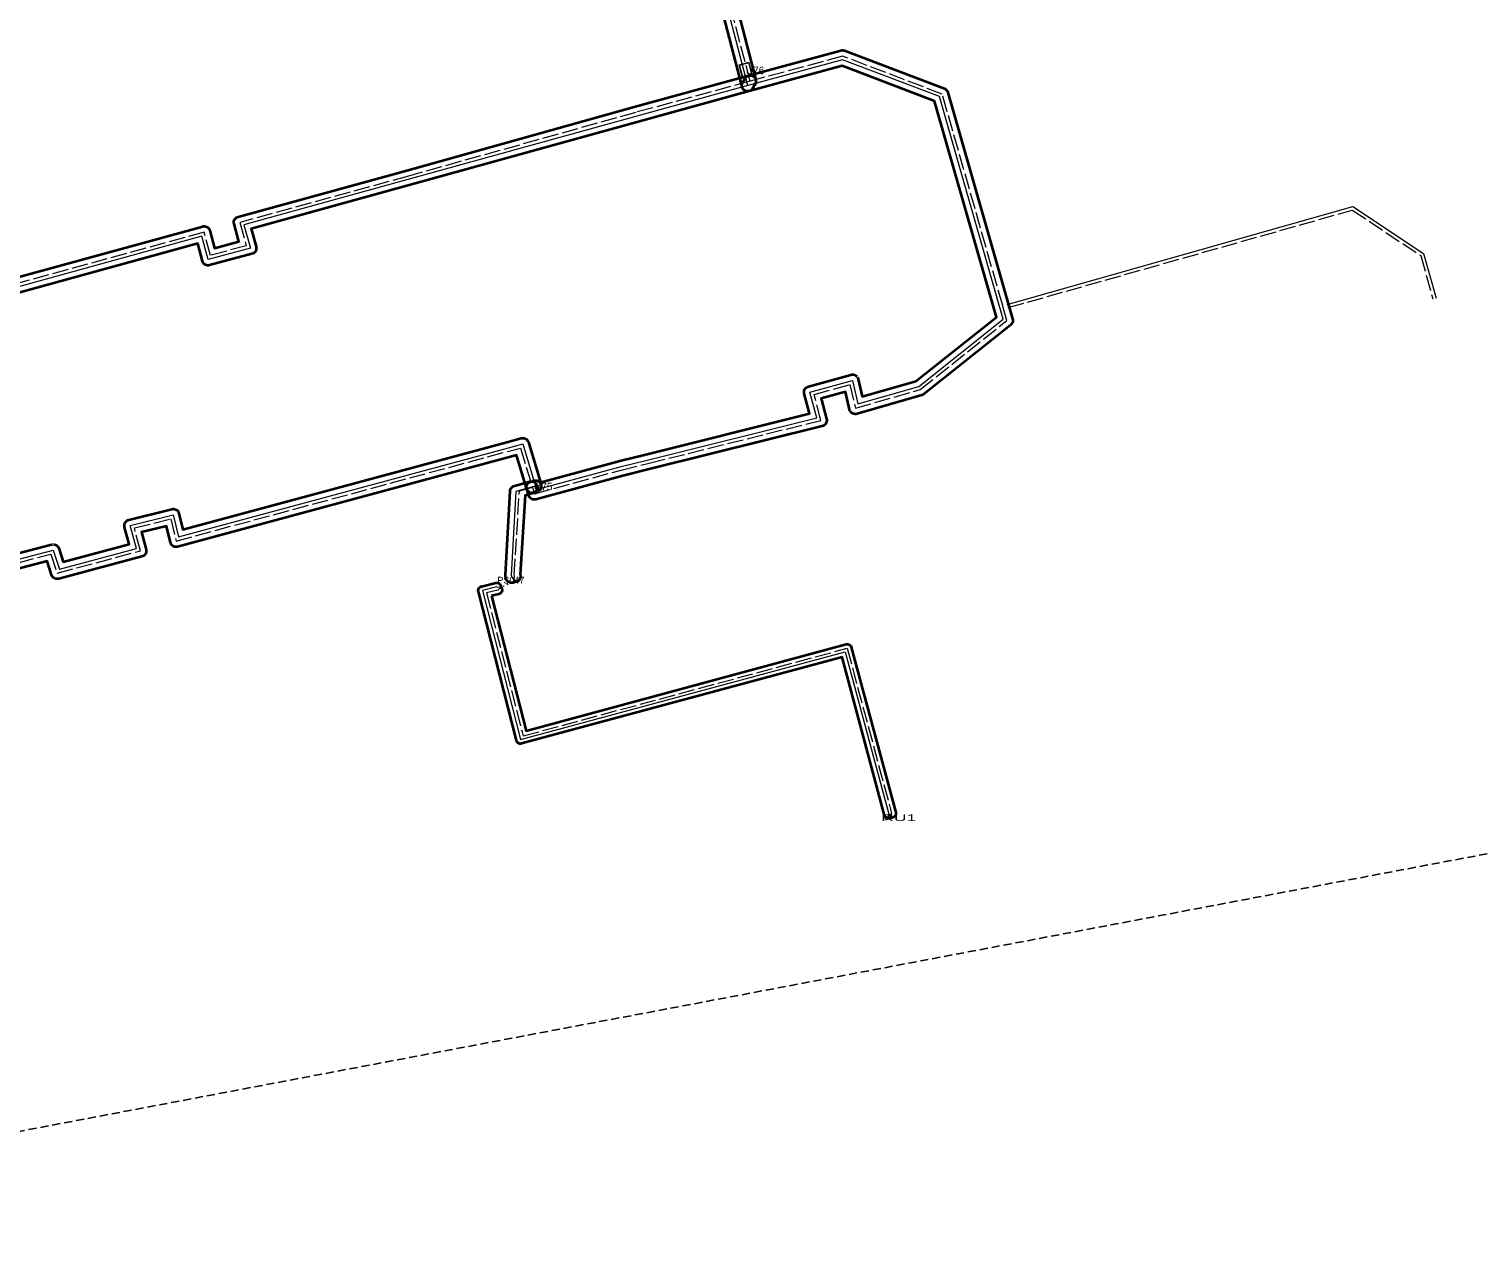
# Model space of a CAD drawing. Extents: x -452602 to -451136, y -1100088 to -1099653.
# Drawn here: x -451526.1 to -451353.5, y -1099905.8 to -1099759.5 of the extents above; entities that cross this region are included whole.
import ezdxf

# ---------------------------------------------------------------- set-up
doc = ezdxf.new("R2010")
doc.units = 0
doc.header["$LTSCALE"] = 0.32
doc.header["$PDMODE"] = 32
doc.header["$PDSIZE"] = 0.16
for name, pattern in [('DOTTED', [1.5, 0.3, -1.2]), ('LONG_DASHED', [7.5, 6, -1.5]), ('MEDIUM_DASHED', [4.5, 3, -1.5])]:
    doc.linetypes.add(name, pattern=pattern)
for name, color, linetype, lineweight in [('2', 7, 'Continuous', 13), ('3', 7, 'Continuous', 25), ('62', 7, 'MEDIUM_DASHED', 25), ('8', 7, 'Continuous', 35)]:
    doc.layers.add(name, color=color, linetype=linetype, lineweight=lineweight)
doc.layers.add('4', color=7, linetype='Continuous')

msp = doc.modelspace()

# ---------------------------------------------------------------- linework, layer by layer
at = {"layer": '2'}
for p, q in [((-451465.807, -1099813.902), (-451466.276, -1099814.026)), ((-451468.623, -1099824.703), (-451468.33, -1099825.077)), ((-451470.4, -1099825.877), (-451469.87, -1099825.911)), ((-451423.766, -1099852.933), (-451424.031, -1099853.49)), ((-451423.766, -1099852.933), (-451423.46, -1099853.339))]:
    msp.add_line(p, q, dxfattribs=at)
at = {"layer": '2', "linetype": 'LONG_DASHED'}
for p, q in [((-451466.266, -1099814.057), (-451466.163, -1099814.028)), ((-451468.33, -1099825.077), (-451468.279, -1099824.611)), ((-451470.266, -1099826.255), (-451469.87, -1099825.911)), ((-451424.031, -1099853.49), (-451423.416, -1099852.842)), ((-451423.46, -1099853.339), (-451423.416, -1099852.842))]:
    msp.add_line(p, q, dxfattribs=at)
at = {"layer": '2', "linetype": 'DOTTED'}
for q in [(-451468.33, -1099825.077), (-451469.87, -1099825.911)]:
    msp.add_line((-451469.133, -1099825.585), q, dxfattribs=at)
at = {"layer": '2'}
for points in [[(-451440.543, -1099766.212), (-451448.402, -1099735.947), (-451449.946, -1099736.35), (-451450.538, -1099734.326), (-451448.936, -1099733.888), (-451454.027, -1099714.285), (-451455.513, -1099714.714), (-451456.072, -1099712.712), (-451454.541, -1099712.309), (-451454.966, -1099710.671)], [(-451465.807, -1099813.902), (-451465.693, -1099814.283), (-451455.431, -1099811.527), (-451452.657, -1099810.837), (-451432.332, -1099805.776), (-451433.135, -1099802.708), (-451428.085, -1099801.307), (-451427.435, -1099804.116), (-451420.193, -1099802.032), (-451410.156, -1099794.026), (-451417.723, -1099767.545), (-451429.284, -1099763.151), (-451440.543, -1099766.212)], [(-451440.543, -1099766.212), (-451500.5, -1099782.791), (-451499.718, -1099785.574), (-451504.756, -1099786.93), (-451505.494, -1099784.161), (-451531.96, -1099791.453), (-451536.46, -1099775.666), (-451566.551, -1099783.675), (-451567.153, -1099781.244), (-451568.797, -1099781.667), (-451568.176, -1099784.107), (-451599.266, -1099792.381), (-451600.66, -1099787.109), (-451609.817, -1099789.576), (-451612.038, -1099780.59)], [(-451409.67, -1099792.266), (-451368.532, -1099780.606), (-451360.12, -1099786.214), (-451358.624, -1099791.515)], [(-451551.827, -1099895.315), (-451558.739, -1099869.548), (-451529.806, -1099861.951), (-451539.465, -1099825.761), (-451523.193, -1099821.5), (-451522.45, -1099823.752), (-451513.289, -1099821.307), (-451514.016, -1099818.579), (-451508.902, -1099817.3), (-451508.266, -1099819.931), (-451469.019, -1099809.326), (-451467.315, -1099808.865), (-451465.807, -1099813.902)], [(-451466.276, -1099814.026), (-451468.121, -1099814.517), (-451468.685, -1099824.471), (-451468.623, -1099824.703)], [(-451470.4, -1099825.877), (-451472.105, -1099826.309), (-451467.574, -1099844.048), (-451428.957, -1099833.619), (-451423.766, -1099852.933)]]:
    msp.add_lwpolyline(points, dxfattribs=at)
at = {"layer": '2', "linetype": 'LONG_DASHED'}
for points in [[(-451440.258, -1099765.721), (-451448.116, -1099735.46), (-451449.671, -1099735.864), (-451450.039, -1099734.603), (-451448.45, -1099734.171), (-451453.744, -1099713.787), (-451455.237, -1099714.217), (-451455.579, -1099712.995), (-451454.053, -1099712.596), (-451454.571, -1099710.599)], [(-451466.163, -1099814.028), (-451465.927, -1099814.795), (-451455.596, -1099811.98), (-451452.27, -1099811.152), (-451431.843, -1099806.067), (-451432.649, -1099802.988), (-451428.38, -1099801.804), (-451427.729, -1099804.618), (-451420.005, -1099802.394), (-451409.699, -1099794.173), (-451410.09, -1099792.8), (-451410.2, -1099792.416), (-451417.394, -1099767.243), (-451429.263, -1099762.73), (-451440.258, -1099765.721)], [(-451440.258, -1099765.721), (-451453.851, -1099769.417), (-451480.917, -1099777.002), (-451500.994, -1099782.511), (-451500.212, -1099785.292), (-451504.472, -1099786.44), (-451505.212, -1099783.669), (-451531.662, -1099790.934), (-451536.175, -1099775.177), (-451566.255, -1099783.181), (-451566.862, -1099780.756), (-451569.284, -1099781.379), (-451568.655, -1099783.82), (-451598.982, -1099791.89), (-451600.376, -1099786.618), (-451609.527, -1099789.083), (-451611.651, -1099780.495)], [(-451409.546, -1099792.646), (-451368.601, -1099781.041), (-451360.465, -1099786.465), (-451359.009, -1099791.624)], [(-451551.433, -1099895.241), (-451558.248, -1099869.833), (-451529.317, -1099862.234), (-451538.976, -1099826.048), (-451523.454, -1099821.982), (-451522.711, -1099824.236), (-451512.799, -1099821.592), (-451513.524, -1099818.868), (-451509.196, -1099817.785), (-451508.559, -1099820.425), (-451468.961, -1099809.725), (-451467.595, -1099809.356), (-451466.163, -1099814.028)], [(-451468.279, -1099824.611), (-451468.318, -1099824.46), (-451467.705, -1099814.46), (-451466.266, -1099814.057)], [(-451470.266, -1099826.255), (-451471.618, -1099826.599), (-451467.396, -1099843.128), (-451467.258, -1099843.608), (-451428.708, -1099833.184), (-451423.416, -1099852.842)]]:
    msp.add_lwpolyline(points, dxfattribs=at)
at = {"layer": '3'}
for points in [[(-451441.13, -1099765.365), (-451441.548, -1099763.801), (-451440.427, -1099763.497), (-451439.997, -1099765.067)], [(-451465.048, -1099814.278), (-451466.6, -1099814.738), (-451466.934, -1099813.625), (-451465.376, -1099813.154)]]:
    msp.add_lwpolyline(points, close=True, dxfattribs=at)
at = {"layer": '4'}
for p in [(-451468.33, -1099825.077), (-451424.031, -1099853.49), (-451423.46, -1099853.339)]:
    msp.add_point(p, dxfattribs=at)
at = {"layer": '62'}
msp.add_lwpolyline([(-451137.485, -1099816.961), (-452572.169, -1100088.267), (-452602.314, -1099919.678), (-451137.485, -1099652.838), (-451136.368, -1099701.963)], close=True, dxfattribs=at)
at = {"layer": '8'}
for points in [[(-451447.439, -1099735.284), (-451439.58, -1099765.545), (-451439.559, -1099765.763), (-451439.606, -1099765.976), (-451439.717, -1099766.165), (-451439.851, -1099766.284), (-451439.892, -1099766.468), (-451440.003, -1099766.657), (-451440.167, -1099766.802), (-451440.368, -1099766.89), (-451440.586, -1099766.911), (-451440.799, -1099766.864), (-451440.988, -1099766.753), (-451441.134, -1099766.589), (-451441.221, -1099766.388), (-451448.904, -1099736.802)], [(-451429.015, -1099762.076), (-451417.145, -1099766.588), (-451417.047, -1099766.634), (-451416.957, -1099766.695), (-451416.878, -1099766.769), (-451416.811, -1099766.854), (-451416.758, -1099766.949), (-451416.72, -1099767.05), (-451409.025, -1099793.98), (-451409.003, -1099794.095), (-451409, -1099794.213), (-451409.016, -1099794.329), (-451409.052, -1099794.441), (-451409.106, -1099794.545), (-451409.177, -1099794.639), (-451409.262, -1099794.72), (-451419.569, -1099802.942), (-451419.644, -1099802.994), (-451419.726, -1099803.036), (-451419.812, -1099803.067), (-451427.536, -1099805.291), (-451427.647, -1099805.314), (-451427.761, -1099805.318), (-451427.873, -1099805.304), (-451427.982, -1099805.271), (-451428.084, -1099805.222), (-451428.177, -1099805.157), (-451428.258, -1099805.077), (-451428.325, -1099804.986), (-451428.377, -1099804.885), (-451428.412, -1099804.776), (-451428.898, -1099802.674), (-451431.797, -1099803.478), (-451431.165, -1099805.889), (-451431.146, -1099805.998), (-451431.144, -1099806.109), (-451431.159, -1099806.218), (-451431.192, -1099806.324), (-451431.24, -1099806.423), (-451431.304, -1099806.514), (-451431.381, -1099806.593), (-451431.47, -1099806.659), (-451431.568, -1099806.711), (-451431.673, -1099806.746), (-451452.101, -1099811.831), (-451455.42, -1099812.657), (-451465.743, -1099815.471), (-451465.861, -1099815.492), (-451465.98, -1099815.493), (-451466.098, -1099815.474), (-451466.211, -1099815.435), (-451466.316, -1099815.377), (-451466.41, -1099815.303), (-451466.489, -1099815.213), (-451466.552, -1099815.111), (-451466.597, -1099815.001), (-451466.832, -1099814.234), (-451466.855, -1099814.124), (-451466.86, -1099814.011), (-451466.847, -1099813.9), (-451466.816, -1099813.792), (-451466.769, -1099813.69), (-451466.706, -1099813.597), (-451466.629, -1099813.516), (-451466.539, -1099813.448), (-451466.44, -1099813.395), (-451466.334, -1099813.358), (-451466.224, -1099813.339), (-451466.125, -1099813.278), (-451466.017, -1099813.234), (-451465.903, -1099813.209), (-451465.787, -1099813.202), (-451465.672, -1099813.215), (-451465.56, -1099813.248), (-451465.455, -1099813.298), (-451465.36, -1099813.365), (-451465.277, -1099813.446), (-451455.613, -1099810.851), (-451455.6, -1099810.848), (-451452.836, -1099810.16), (-451452.825, -1099810.157), (-451433.189, -1099805.268), (-451433.813, -1099802.885), (-451433.833, -1099802.766), (-451433.833, -1099802.645), (-451433.811, -1099802.526), (-451433.77, -1099802.412), (-451433.71, -1099802.307), (-451433.632, -1099802.214), (-451433.54, -1099802.136), (-451433.436, -1099802.075), (-451433.323, -1099802.033), (-451428.272, -1099800.632), (-451428.161, -1099800.611), (-451428.048, -1099800.607), (-451427.936, -1099800.622), (-451427.828, -1099800.655), (-451427.727, -1099800.705), (-451427.635, -1099800.77), (-451427.554, -1099800.85)], [(-451427.488, -1099800.941), (-451427.437, -1099801.041), (-451427.402, -1099801.149), (-451426.92, -1099803.24), (-451420.521, -1099801.398), (-451410.958, -1099793.77), (-451418.3, -1099768.074), (-451429.32, -1099763.886), (-451440.36, -1099766.888), (-451440.479, -1099766.91), (-451440.601, -1099766.91), (-451440.721, -1099766.89), (-451440.835, -1099766.849), (-451440.941, -1099766.789), (-451441.035, -1099766.711), (-451441.114, -1099766.619), (-451441.175, -1099766.514), (-451441.218, -1099766.4), (-451441.24, -1099766.281), (-451441.241, -1099766.159), (-451441.222, -1099766.039), (-451441.182, -1099765.925), (-451441.122, -1099765.819), (-451441.045, -1099765.725), (-451440.954, -1099765.645), (-451440.931, -1099765.528), (-451440.888, -1099765.416), (-451440.827, -1099765.313), (-451440.749, -1099765.222), (-451440.657, -1099765.146), (-451440.553, -1099765.086), (-451440.441, -1099765.045), (-451429.447, -1099762.055), (-451429.339, -1099762.035), (-451429.229, -1099762.031), (-451429.12, -1099762.045), (-451429.015, -1099762.076)], [(-451531.179, -1099790.075), (-451505.397, -1099782.994), (-451505.289, -1099782.974), (-451505.178, -1099782.97), (-451505.069, -1099782.984), (-451504.963, -1099783.015), (-451504.863, -1099783.062), (-451504.772, -1099783.124), (-451504.692, -1099783.2), (-451504.625, -1099783.288), (-451504.572, -1099783.385), (-451504.535, -1099783.489), (-451503.976, -1099785.582), (-451501.077, -1099784.8), (-451501.668, -1099782.698), (-451501.689, -1099782.59), (-451501.693, -1099782.48), (-451501.679, -1099782.371), (-451501.649, -1099782.265), (-451501.602, -1099782.166), (-451501.541, -1099782.075), (-451501.465, -1099781.994), (-451501.379, -1099781.927), (-451501.282, -1099781.874), (-451501.179, -1099781.836), (-451481.104, -1099776.327), (-451454.038, -1099768.742), (-451440.441, -1099765.045), (-451440.322, -1099765.023), (-451440.2, -1099765.023), (-451440.08, -1099765.043), (-451439.966, -1099765.084), (-451439.86, -1099765.144), (-451439.766, -1099765.222)], [(-451439.688, -1099765.314), (-451439.626, -1099765.419), (-451439.583, -1099765.533), (-451439.561, -1099765.652), (-451439.56, -1099765.774), (-451439.579, -1099765.894), (-451439.619, -1099766.008), (-451439.679, -1099766.114), (-451439.755, -1099766.208), (-451439.847, -1099766.288), (-451439.87, -1099766.405), (-451439.913, -1099766.516), (-451439.973, -1099766.619), (-451440.051, -1099766.71), (-451440.142, -1099766.786), (-451440.245, -1099766.846), (-451440.357, -1099766.887), (-451499.636, -1099783.279), (-451499.044, -1099785.385), (-451499.021, -1099785.502), (-451499.019, -1099785.62), (-451499.037, -1099785.738), (-451499.075, -1099785.85), (-451499.13, -1099785.955), (-451499.203, -1099786.049)], [(-451499.203, -1099786.049), (-451499.275, -1099786.116), (-451499.355, -1099786.173), (-451499.443, -1099786.218), (-451499.536, -1099786.25), (-451504.574, -1099787.606), (-451504.694, -1099787.627), (-451504.816, -1099787.628), (-451504.936, -1099787.607), (-451505.051, -1099787.565), (-451505.156, -1099787.504), (-451505.25, -1099787.426), (-451505.329, -1099787.333), (-451505.39, -1099787.227), (-451505.432, -1099787.113), (-451505.988, -1099785.024), (-451531.774, -1099792.128)], [(-451523.137, -1099820.802), (-451523.022, -1099820.821), (-451522.911, -1099820.859), (-451522.808, -1099820.914), (-451522.716, -1099820.987), (-451522.637, -1099821.074), (-451522.574, -1099821.172), (-451522.528, -1099821.28), (-451521.992, -1099822.905), (-451514.146, -1099820.811), (-451514.693, -1099818.759), (-451514.713, -1099818.65), (-451514.715, -1099818.539), (-451514.7, -1099818.429), (-451514.668, -1099818.323), (-451514.619, -1099818.223), (-451514.556, -1099818.132), (-451514.479, -1099818.053), (-451514.39, -1099817.986), (-451514.291, -1099817.935), (-451514.186, -1099817.899), (-451509.07, -1099816.62), (-451508.961, -1099816.602), (-451508.851, -1099816.601), (-451508.741, -1099816.618), (-451508.637, -1099816.652), (-451508.538, -1099816.701), (-451508.449, -1099816.766), (-451508.37, -1099816.843), (-451508.306, -1099816.932), (-451508.255, -1099817.03), (-451508.221, -1099817.135), (-451507.755, -1099819.067), (-451469.202, -1099808.65), (-451467.498, -1099808.19), (-451467.38, -1099808.168), (-451467.26, -1099808.168), (-451467.142, -1099808.187), (-451467.029, -1099808.227), (-451466.924, -1099808.285), (-451466.831, -1099808.36), (-451466.751, -1099808.451), (-451466.689, -1099808.553), (-451466.645, -1099808.664)], [(-451466.645, -1099808.664), (-451465.137, -1099813.701), (-451465.113, -1099813.813), (-451465.108, -1099813.926), (-451465.121, -1099814.039), (-451465.152, -1099814.149), (-451465.201, -1099814.252), (-451465.266, -1099814.346), (-451465.345, -1099814.428), (-451465.436, -1099814.496), (-451465.538, -1099814.548), (-451465.646, -1099814.583), (-451465.759, -1099814.6), (-451465.862, -1099814.661), (-451465.975, -1099814.703), (-451466.093, -1099814.725), (-451466.213, -1099814.727), (-451466.331, -1099814.708), (-451466.445, -1099814.669), (-451466.55, -1099814.611), (-451466.644, -1099814.537), (-451466.724, -1099814.447), (-451466.787, -1099814.345), (-451466.832, -1099814.234), (-451468.066, -1099810.208), (-451468.778, -1099810.4), (-451508.376, -1099821.1), (-451508.486, -1099821.121), (-451508.597, -1099821.123), (-451508.708, -1099821.108), (-451508.815, -1099821.076), (-451508.915, -1099821.027), (-451509.007, -1099820.962), (-451509.087, -1099820.884), (-451509.153, -1099820.794), (-451509.204, -1099820.695), (-451509.239, -1099820.589), (-451509.71, -1099818.636), (-451512.665, -1099819.375), (-451512.123, -1099821.411), (-451512.102, -1099821.532), (-451512.102, -1099821.654), (-451512.124, -1099821.774), (-451512.166, -1099821.888), (-451512.227, -1099821.994), (-451512.305, -1099822.087), (-451512.399, -1099822.165), (-451512.504, -1099822.226), (-451512.619, -1099822.268), (-451522.531, -1099824.912), (-451522.647, -1099824.932), (-451522.764, -1099824.934), (-451522.88, -1099824.915), (-451522.992, -1099824.877), (-451523.095, -1099824.821), (-451523.188, -1099824.749), (-451523.267, -1099824.662), (-451523.33, -1099824.563), (-451523.376, -1099824.455), (-451523.913, -1099822.825), (-451538.118, -1099826.546)], [(-451539.643, -1099825.084), (-451523.37, -1099820.822), (-451523.255, -1099820.802)]]:
    msp.add_lwpolyline(points, dxfattribs=at)
for points in [[(-451468.568, -1099825.4), (-451468.689, -1099825.4), (-451468.808, -1099825.378), (-451468.922, -1099825.336), (-451469.027, -1099825.275), (-451469.119, -1099825.196), (-451469.197, -1099825.103), (-451469.258, -1099824.998), (-451469.299, -1099824.884), (-451469.361, -1099824.65), (-451469.381, -1099824.543), (-451469.383, -1099824.433), (-451468.82, -1099814.477), (-451468.805, -1099814.368), (-451468.773, -1099814.263), (-451468.726, -1099814.164), (-451468.663, -1099814.074), (-451468.588, -1099813.995), (-451468.5, -1099813.929), (-451468.404, -1099813.877), (-451468.3, -1099813.84), (-451466.456, -1099813.35), (-451466.336, -1099813.328), (-451466.215, -1099813.327), (-451466.095, -1099813.347), (-451465.98, -1099813.387), (-451465.875, -1099813.447), (-451465.781, -1099813.524), (-451465.701, -1099813.616), (-451465.639, -1099813.721), (-451465.596, -1099813.835), (-451465.583, -1099813.884), (-451465.574, -1099813.935), (-451465.563, -1099814.049), (-451465.571, -1099814.163), (-451465.598, -1099814.275), (-451465.642, -1099814.381), (-451465.704, -1099814.478), (-451465.78, -1099814.564), (-451465.869, -1099814.636), (-451465.969, -1099814.692), (-451466.077, -1099814.731), (-451467.037, -1099815), (-451467.613, -1099824.391), (-451467.602, -1099824.433), (-451467.582, -1099824.542), (-451467.58, -1099824.653), (-451467.595, -1099824.763), (-451467.628, -1099824.87), (-451467.677, -1099824.969), (-451467.741, -1099825.06), (-451467.819, -1099825.14), (-451467.909, -1099825.206), (-451468.007, -1099825.257), (-451468.113, -1099825.291), (-451468.223, -1099825.309), (-451468.278, -1099825.311), (-451468.37, -1099825.355), (-451468.467, -1099825.385)], [(-451471.01, -1099826.96), (-451466.913, -1099842.997), (-451428.839, -1099832.701), (-451428.761, -1099832.686), (-451428.683, -1099832.684), (-451428.605, -1099832.694), (-451428.53, -1099832.716), (-451428.459, -1099832.75), (-451428.394, -1099832.794), (-451428.337, -1099832.848), (-451428.289, -1099832.911), (-451428.252, -1099832.98), (-451428.225, -1099833.054), (-451422.934, -1099852.712), (-451422.919, -1099852.798), (-451422.919, -1099852.885), (-451422.934, -1099852.97), (-451422.964, -1099853.052), (-451423.008, -1099853.127), (-451423.063, -1099853.194), (-451423.13, -1099853.25), (-451423.205, -1099853.293), (-451423.287, -1099853.323), (-451423.373, -1099853.338), (-451423.459, -1099853.338), (-451423.47, -1099853.336), (-451423.539, -1099853.379), (-451423.614, -1099853.41), (-451423.692, -1099853.428), (-451423.773, -1099853.433), (-451423.854, -1099853.426), (-451423.932, -1099853.405), (-451424.006, -1099853.372), (-451424.073, -1099853.328), (-451424.133, -1099853.274), (-451424.183, -1099853.21), (-451424.222, -1099853.139), (-451424.249, -1099853.063), (-451429.31, -1099834.232), (-451467.443, -1099844.531), (-451467.521, -1099844.546), (-451467.6, -1099844.548), (-451467.679, -1099844.537), (-451467.755, -1099844.515), (-451467.826, -1099844.48), (-451467.891, -1099844.435), (-451467.948, -1099844.38), (-451467.995, -1099844.317), (-451468.033, -1099844.247), (-451468.058, -1099844.172), (-451472.589, -1099826.433), (-451472.603, -1099826.356), (-451472.604, -1099826.277), (-451472.592, -1099826.2), (-451472.569, -1099826.125), (-451472.534, -1099826.054), (-451472.489, -1099825.99), (-451472.435, -1099825.934), (-451472.372, -1099825.887), (-451472.302, -1099825.85), (-451472.228, -1099825.825), (-451470.523, -1099825.392), (-451470.439, -1099825.379), (-451470.353, -1099825.38), (-451470.269, -1099825.396), (-451470.189, -1099825.426), (-451470.115, -1099825.469), (-451470.049, -1099825.524), (-451469.994, -1099825.59), (-451469.951, -1099825.664), (-451469.921, -1099825.745), (-451469.906, -1099825.829), (-451469.905, -1099825.915), (-451469.855, -1099825.975), (-451469.813, -1099826.051), (-451469.784, -1099826.133), (-451469.77, -1099826.219), (-451469.772, -1099826.305), (-451469.788, -1099826.391), (-451469.818, -1099826.472), (-451469.862, -1099826.547), (-451469.919, -1099826.613), (-451469.986, -1099826.668), (-451470.061, -1099826.711), (-451470.143, -1099826.74)]]:
    msp.add_lwpolyline(points, close=True, dxfattribs=at)

# ---------------------------------------------------------------- texts
at = {"layer": '3'}
for s, p in [('U76 ', (-451440.775, -1099764.882)), ('U75 ', (-451465.989, -1099814.397))]:
    msp.add_text(s, height=0.9, dxfattribs=at).set_placement(p)
at = {"layer": '4'}
msp.add_text('PS047 ', height=0.8, dxfattribs=at).set_placement((-451470.33, -1099825.477))
at = {"layer": '4', "width": 1.95}
msp.add_text('RU1 ', height=0.8, dxfattribs=at).set_placement((-451424.66, -1099853.739))

doc.saveas('drawing.dxf')
